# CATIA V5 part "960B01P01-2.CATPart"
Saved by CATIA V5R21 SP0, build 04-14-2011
Part number: 960B01P01-2
Bounding box of the stored display mesh (mm): x -33.4 to 33.4, y 56.85 to 158.05, z -8 to 13.3
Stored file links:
  C:\Users\ALI OZGUN\Desktop\alhan\960B01P01-2.CATPart
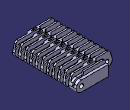
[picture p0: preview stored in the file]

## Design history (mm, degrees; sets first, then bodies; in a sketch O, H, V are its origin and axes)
Body1 (main body)
Body2
  Solid1: solid without history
